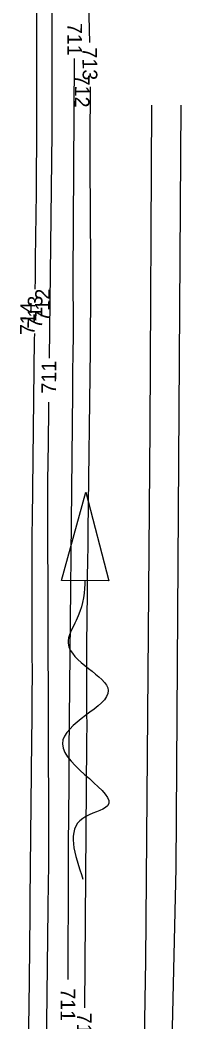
# Model space of a CAD drawing. Extents: x -468548933 to 3387700, y -306089263 to 1207014.
# Drawn here: x 1835227.1 to 1835270.9, y 536498.1 to 536770.1 of the extents above; entities that cross this region are included whole.
import ezdxf

# ---------------------------------------------------------------- set-up
doc = ezdxf.new("R2010")
doc.units = 0
for name, color, linetype in [('DT_X_Contour_Minor', 7, 'Continuous'), ('Level 19', 7, 'Continuous'), ('Level 56', 7, 'Continuous')]:
    doc.layers.add(name, color=color, linetype=linetype)

msp = doc.modelspace()

# ---------------------------------------------------------------- linework, layer by layer
at = {"layer": 'DT_X_Contour_Minor'}
for points in [[(1835231.23, 536696.99), (1835231.27, 536699.78), (1835231.33, 536705.25), (1835231.54, 536723.12), (1835231.58, 536726.95), (1835231.61, 536730.78), (1835231.63, 536734.61), (1835231.64, 536738.44), (1835231.7, 536811.98)], [(1835245.63, 536778.38), (1835245.97, 536763.96)], [(1835235.77, 536773.41), (1835235.78, 536769.67), (1835235.79, 536765.94), (1835235.79, 536762.2), (1835235.78, 536750), (1835235.77, 536747.39), (1835235.76, 536744.77), (1835235.74, 536742.16), (1835235.71, 536739.54), (1835235, 536678.32)], [(1835240.15, 536509.65), (1835240.27, 536539.31), (1835240.29, 536542.43), (1835240.3, 536545.55), (1835240.32, 536548.67), (1835240.35, 536551.79), (1835240.46, 536565.1), (1835240.46, 536565.73), (1835240.47, 536566.35), (1835240.47, 536566.98), (1835240.46, 536567.61), (1835240.46, 536569.66), (1835240.46, 536570.1), (1835240.46, 536570.54), (1835240.46, 536570.98), (1835240.46, 536571.42), (1835241.42, 536669.16), (1835241.44, 536671.41), (1835241.46, 536673.65), (1835241.49, 536675.9), (1835241.52, 536678.15), (1835241.61, 536685.82), (1835241.62, 536687.23), (1835241.63, 536688.63), (1835241.63, 536690.04), (1835241.63, 536691.45), (1835241.6, 536696.04), (1835241.6, 536697.02), (1835241.6, 536698.01), (1835241.6, 536698.99), (1835241.6, 536699.98), (1835241.95, 536759.64)], [(1835246.14, 536751.96), (1835246.14, 536749.51), (1835246.08, 536739.67), (1835246.07, 536737.56), (1835246.07, 536735.45), (1835246.07, 536733.34), (1835246.08, 536731.23), (1835246.24, 536703.94), (1835246.26, 536698.09), (1835246.25, 536692.24), (1835246.22, 536686.39), (1835246.16, 536680.54), (1835245.56, 536631.54), (1835245.51, 536627.36), (1835245.46, 536623.17), (1835245.41, 536618.98), (1835245.37, 536614.79), (1835245.23, 536600.54), (1835245.21, 536597.89), (1835245.2, 536595.24), (1835245.2, 536592.58), (1835245.2, 536589.93), (1835245.23, 536581.27), (1835245.24, 536579.41), (1835245.24, 536577.55), (1835245.23, 536575.7), (1835245.22, 536573.84), (1835244.62, 536501.97)], [(1835228.14, 536435.01), (1835229.23, 536482.95), (1835229.33, 536487.76), (1835229.42, 536492.57), (1835229.5, 536497.39), (1835229.56, 536502.2), (1835229.74, 536517.93), (1835229.78, 536521.3), (1835229.82, 536524.67), (1835229.86, 536528.04), (1835229.89, 536531.42), (1835230.34, 536574.57), (1835230.4, 536580.55), (1835230.43, 536586.52), (1835230.44, 536592.5), (1835230.43, 536598.47), (1835230.36, 536617.99), (1835230.36, 536622.17), (1835230.37, 536626.35), (1835230.4, 536630.53), (1835230.44, 536634.72), (1835231.06, 536683.36), (1835231.08, 536684.99)], [(1835234.86, 536666.32), (1835234.8, 536661.18), (1835234.77, 536658.75), (1835234.74, 536656.32), (1835234.71, 536653.9), (1835234.68, 536651.47), (1835234.57, 536643.54), (1835234.56, 536641.84), (1835234.55, 536640.14), (1835234.54, 536638.44), (1835234.54, 536636.74), (1835234.83, 536550.05), (1835234.84, 536547.94), (1835234.83, 536545.84), (1835234.82, 536543.74), (1835234.8, 536541.63), (1835234.73, 536534.76), (1835234.72, 536533.28), (1835234.7, 536531.81), (1835234.68, 536530.34), (1835234.67, 536528.87), (1835233.76, 536451.31)]]:
    msp.add_lwpolyline(points, dxfattribs=at)
at = {"layer": 'Level 56'}
for p, q in [((1835238.36, 536617.97), (1835244.98, 536641.93)), ((1835244.98, 536641.93), (1835251.24, 536617.88)), ((1835251.24, 536617.88), (1835238.36, 536617.97))]:
    msp.add_line(p, q, dxfattribs=at)
for points in [[(1835262.92, 536746.95), (1835262.45, 536659.53), (1835261.24, 536514.73), (1835259.56, 536412.94), (1835256.79, 536331.65)], [(1835264.78, 536331.38), (1835269.59, 536539.91), (1835270.92, 536746.94)]]:
    msp.add_lwpolyline(points, dxfattribs=at)
msp.add_spline([(1835244.74, 536617.95), (1835244.73, 536617), (1835242.41, 536607.14), (1835240.19, 536600.91), (1835251.12, 536588.11), (1835238.64, 536573.64), (1835250.9, 536556.76), (1835244.17, 536553.4), (1835244.23, 536536.93)], degree=3, dxfattribs=at)

# ---------------------------------------------------------------- texts
at = {"layer": 'Level 19'}
for s, rotation, p in [('711', 269.8279, (1835239.99, 536769.3)), ('713', 270.8162, (1835244.03, 536762.61)), ('712', 269.6684, (1835242.05, 536755.25)), ('713', 89.2889, (1835233.1, 536686.29)), ('712', 89.328, (1835235.12, 536688.2)), ('714', 89.2678, (1835231.07, 536684.51)), ('711', 89.328, (1835236.88, 536668.64)), ('711', 269.7734, (1835238.15, 536507.31)), ('713', 269.5339, (1835242.61, 536500.67))]:
    msp.add_text(s, height=4, rotation=rotation, dxfattribs=at).set_placement(p)

doc.saveas('drawing.dxf')
